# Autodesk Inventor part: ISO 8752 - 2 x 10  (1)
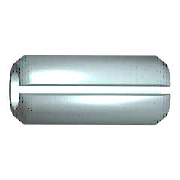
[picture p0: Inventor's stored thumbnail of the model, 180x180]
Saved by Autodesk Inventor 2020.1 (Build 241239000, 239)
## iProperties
Created: 2019-01
Part Number: ISO 8752 - 2 x 10  (1)
Material: Stainless Steel, Austenitic
Description: Spring-Type Straight Pin
Document SubType Name: Modeling
Standard: ISO 8752
Designer: Safarabadi
Standards Organization: DIN
Language: en-US
Size Designation: 2 x 10
Categories: <MemberInstance><Categories><Category DisplayName="Fasteners" InternalName="e4da775c-781d-43d5-af7c-5136215cf5a6" Mnemonic="FSTN"><Category DisplayName="Pins" I
Density: 8 g/cm^3
Appearance: Semi-Polished
IsCustomPart: 1
Author: Safarabadi
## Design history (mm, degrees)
sketch "Sketch1"
  geometry: L1 (0, 0.6)-(0, 0.906); L2 (0, 0.906)-(0.35, 1); L3 (0.35, 1)-(9.65, 1); L4 (9.65, 1)-(10, 0.906); L5 (10, 0.906)-(10, 0.6); L6 (10, 0)-(0, 0); L7 (0, 0.6)-(10, 0.6); L8 (0, 0.6)-(0, 0); L9 (10, 0.6)-(10, 0); L10 (0, 1.5)-(0, -0.25) reference; L11 (-2, 0)-(12, 0) reference
  constraints: 18 end point, 3 parallel, 3 perpendicular, 1 coincident, 1 point on line, 1 vertical
  dimensions: "d0" = 10 distance between parallel lines of L5 L1 (= NLG); "d1" = 2 diameter of L3 L6 (= NND); "d2" = 1.2 diameter of L7 L6 (= NND - 2 x SD); "d3" = 15 deg angle of L3 L2 (= FAWI); "d4" = 15 deg angle of L4 L3 (= FAWI); "d7" = 0.09378 vertical distance of L2.end L1.end (computed from SD, FAWI, PHH); "d8" = 0.09378 vertical distance of L3.end L4.end (computed from SD, FAWI, PHH1)
revolve "Body" sketch "Sketch1" stored, may be unused: angle "d10" = 90 deg
node "IDS_WORKPLANE{1}"
sketch "Sketch2"
  geometry: L1 (-0.075, 0.595)-(-0.125, 0.992); L2 (0.075, 0.595)-(0.125, 0.992); L3 (0, 1.5)-(0, -0.25) reference; L4 (-0.219, 0)-(0.219, 0) reference; A1 r 1 centre (0, 0) between (0.125, 0.992) and (-0.125, 0.992); A2 r 0.6 centre (0, 0) between (0.075, 0.595) and (-0.075, 0.595); 1 further point
  constraints: 4 end point, 4 point on circle, 2 centre point, 2 coincident, 2 horizontal alignment, 1 other
  dimensions: "d11" = 1 radius of A1 (= 0.5 x NND); "d12" = 0.6 radius of A2 (= -SD + 0.5 x NND); "d14" = 0.4 distance of L1.start L1.end (= SD); "d15" = 7.2 deg angle of L3 L1
extrude "Cut" cut sketch "Sketch2" stored distance "d5" = 10 (= NLG); taper "d6" = 0 deg
body "Solid1"
other parameters: "NND" = 2 [user parameter; used in 4 equation terms], "NLG" = 10 [user parameter; used in 3 equation terms], "SD" = 0.4 [user parameter; used in 5 equation terms], "PHH" = 0.35 [user parameter; used in 1 equation term], "PHH1" = 0.35 [user parameter; used in 1 equation term], "FAWI" = 15 deg [user parameter; used in 4 equation terms], "d9" = 5 (= 0.5 x NLG), "d31" = 0, "d32" = 0, "d33" = 0, "NND1" = 2.4 [user parameter]
